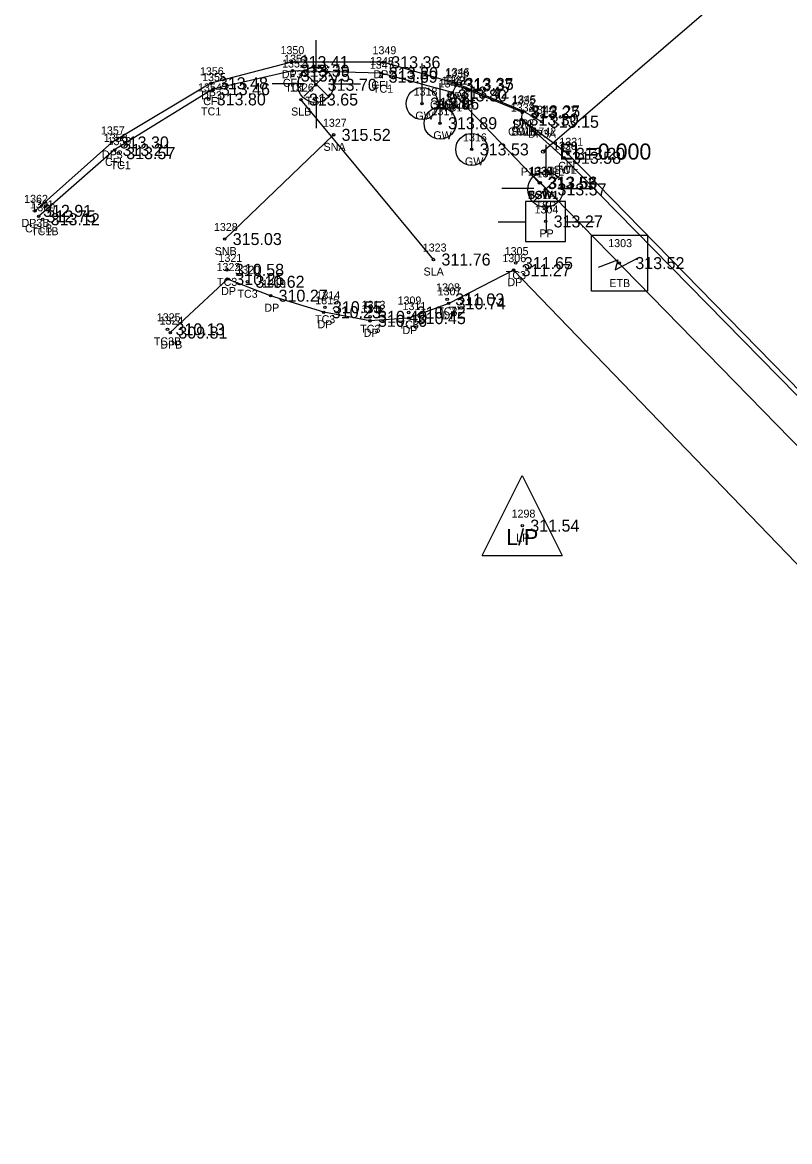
# Model space of a CAD drawing. Extents: x 1970076 to 1971136, y 803126 to 804215.
# Drawn here: x 1970552 to 1970647.9, y 803383.6 to 803523.4 of the extents above; entities that cross this region are included whole.
import ezdxf

# ---------------------------------------------------------------- set-up
doc = ezdxf.new("R2010")
doc.units = 0
for name, color, linetype in [('RD_EX_BldgApp', 7, 'Continuous'), ('RD_EX_BldgApp_txCode', 7, 'Continuous'), ('RD_EX_Conc', 7, 'Continuous'), ('RD_EX_Conc_txCode', 7, 'Continuous'), ('RD_EX_DR_Pipe', 7, 'Continuous'), ('RD_EX_DR_Pipe_txCode', 7, 'Continuous'), ('RD_EX_Driveway', 7, 'Continuous'), ('RD_EX_Driveway_txCode', 7, 'Continuous'), ('RD_EX_SU_Pole', 7, 'Continuous'), ('RD_EX_TX_BldgApp_ELEV', 7, 'Continuous'), ('RD_EX_TX_Conc_ELEV', 7, 'Continuous'), ('RD_EX_TX_Driveway_ELEV', 7, 'Continuous'), ('RD_EX_TX_UT_ELEV', 7, 'Continuous'), ('RD_EX_TX_VEG_ELEV', 7, 'Continuous'), ('RD_EX_UT', 7, 'Continuous'), ('RD_EX_UT_txCode', 7, 'Continuous'), ('RD_EX_VEG', 7, 'Continuous'), ('RD_EX_VEG_txCode', 7, 'Continuous'), ('RD_HC_Survey_ELEV', 7, 'Continuous'), ('RD_SMD_Locator', 7, 'Continuous'), ('RD_TX_Pipe_ElevEX', 7, 'Continuous')]:
    doc.layers.add(name, color=color, linetype=linetype)

msp = doc.modelspace()

# ---------------------------------------------------------------- linework, layer by layer
at = {"layer": 'RD_EX_BldgApp'}
msp.add_line((1970590.93, 803509.37), (1970577.32, 803496.35), dxfattribs=at)
at = {"layer": 'RD_EX_Conc'}
for points in [[(1970605.78, 803514.65), (1970596.84, 803517.08), (1970585.8, 803517.37), (1970575.84, 803515.08), (1970563.55, 803507.49), (1970554.05, 803499.18)], [(1970741.86, 803386.33), (1970712.13, 803414.37), (1970659.98, 803465.47), (1970619.72, 803506.5), (1970614.41, 803511.28), (1970614.52, 803512.19), (1970606.23, 803515.56), (1970605.78, 803514.65)], [(1970738.49, 803383.57), (1970738.35, 803383.61), (1970709.03, 803411.19), (1970656.75, 803462.47), (1970616.75, 803503.4), (1970616.66, 803503.34), (1970605.78, 803514.65)], [(1970742.28, 803386.82), (1970712.72, 803414.79), (1970660.39, 803465.9), (1970620.21, 803507), (1970614.41, 803511.28)]]:
    msp.add_lwpolyline(points, dxfattribs=at)
at = {"layer": 'RD_EX_DR_Pipe'}
msp.add_line((1970664.76, 803548.24), (1970617.11, 803507.28), dxfattribs=at)
at = {"layer": 'RD_EX_Driveway'}
for points in [[(1970616.95, 803511), (1970614.61, 803512.31), (1970606.31, 803515.73), (1970597.14, 803518.44), (1970585.68, 803518.45), (1970575.59, 803515.81), (1970563.2, 803508.42), (1970553.62, 803499.87)], [(1970649.82, 803454.73), (1970613.43, 803492.46), (1970605.31, 803488.31), (1970600.32, 803486.47), (1970595.47, 803486.13), (1970589.7, 803487.2), (1970583.05, 803489.27), (1970577.65, 803491.35), (1970570.52, 803484.66)]]:
    msp.add_lwpolyline(points, dxfattribs=at)
at = {"layer": 'RD_EX_SU_Pole'}
for p, q in [((1970588.76, 803517.19), (1970588.76, 803521.19)), ((1970590.26, 803517.19), (1970587.26, 803514.19)), ((1970587.26, 803517.19), (1970590.26, 803514.19)), ((1970587.23, 803515.74), (1970583.23, 803515.74)), ((1970590.27, 803515.75), (1970594.29, 803515.75)), ((1970588.76, 803514.19), (1970588.76, 803510.19)), ((1970617.48, 803504.12), (1970617.48, 803508.12)), ((1970618.98, 803504.12), (1970615.98, 803501.12)), ((1970615.98, 803504.12), (1970618.98, 803501.12)), ((1970615.96, 803502.67), (1970611.96, 803502.67)), ((1970619, 803502.68), (1970623.01, 803502.68)), ((1970617.48, 803501.12), (1970617.48, 803497.12))]:
    msp.add_line(p, q, dxfattribs=at)
for centre in [(1970588.69, 803515.62), (1970617.41, 803502.55)]:
    msp.add_circle(centre, 2.22, dxfattribs=at)
at = {"layer": 'RD_EX_UT'}
for p, q in [((1970601.99, 803513.27), (1970601.99, 803518.27)), ((1970604.23, 803510.82), (1970604.23, 803515.82)), ((1970608.19, 803507.55), (1970608.19, 803512.55)), ((1970619.92, 803501.06), (1970614.92, 803501.06)), ((1970614.92, 803501.06), (1970614.92, 803496.06)), ((1970619.92, 803496.06), (1970619.92, 803501.06)), ((1970611.49, 803498.5), (1970614.96, 803498.5)), ((1970619.85, 803498.5), (1970623.49, 803498.5)), ((1970614.92, 803496.06), (1970619.92, 803496.06)), ((1970609.51, 803456.81), (1970614.51, 803466.81)), ((1970614.51, 803466.81), (1970619.51, 803456.81)), ((1970609.51, 803456.81), (1970619.51, 803456.81))]:
    msp.add_line(p, q, dxfattribs=at)
msp.add_lwpolyline([(1970623.14, 803489.84), (1970623.14, 803496.84), (1970630.14, 803496.84), (1970630.14, 803489.84)], close=True, dxfattribs=at)
msp.add_lwpolyline([(1970624.04, 803492.84), (1970626.46, 803493.74), (1970626.11, 803492.49), (1970629.16, 803494.09)], dxfattribs=at)
for centre in [(1970601.99, 803513.27), (1970604.23, 803510.82), (1970608.19, 803507.55)]:
    msp.add_circle(centre, 2, dxfattribs=at)
at = {"layer": 'RD_EX_VEG'}
msp.add_line((1970603.41, 803493.79), (1970586.85, 803513.78), dxfattribs=at)
at = {"layer": 'RD_SMD_Locator'}
for centre, radius in [((1970585.68, 803518.45), 0.15), ((1970585.8, 803517.37), 0.15), ((1970596.84, 803517.08), 0.15), ((1970597.14, 803518.44), 0.15), ((1970575.59, 803515.81), 0.15), ((1970585.83, 803516.78), 0.15), ((1970596.8, 803516.63), 0.15), ((1970606.31, 803515.73), 0.15), ((1970575.84, 803515.08), 0.15), ((1970588.69, 803515.62), 0.15), ((1970605.45, 803514.29), 0.15), ((1970605.78, 803514.65), 0.15), ((1970605.78, 803514.65), 0.15), ((1970605.78, 803514.65), 0.15), ((1970606.23, 803515.56), 0.15), ((1970575.32, 803513.8), 0.15), ((1970586.85, 803513.78), 0.15), ((1970601.99, 803513.27), 0.15), ((1970614.52, 803512.19), 0.15), ((1970614.61, 803512.31), 0.15), ((1970604.23, 803510.82), 0.15), ((1970614.41, 803511.28), 0.15), ((1970614.41, 803511.28), 0.15), ((1970614.41, 803511.28), 0.15), ((1970616.95, 803511), 0.15), ((1970590.93, 803509.37), 0.15), ((1970563.2, 803508.42), 0.15), ((1970563.55, 803507.49), 0.15), ((1970608.19, 803507.55), 0.15), ((1970617.11, 803507.28), 0.2), ((1970564.01, 803507.08), 0.15), ((1970619.72, 803506.5), 0.15), ((1970619.72, 803506.5), 0.15), ((1970620.21, 803507), 0.15), ((1970616.66, 803503.34), 0.15), ((1970616.66, 803503.34), 0.15), ((1970616.75, 803503.4), 0.15), ((1970617.41, 803502.55), 0.15), ((1970553.62, 803499.87), 0.15), ((1970554.05, 803499.18), 0.15), ((1970554.57, 803498.82), 0.15), ((1970617.43, 803498.55), 0.15), ((1970577.32, 803496.35), 0.15), ((1970603.41, 803493.79), 0.15), ((1970613.7, 803493.34), 0.15), ((1970626.64, 803493.34), 0.15), ((1970577.6, 803492.5), 0.15), ((1970613.43, 803492.46), 0.15), ((1970577.65, 803491.35), 0.15), ((1970580.16, 803491.01), 0.15), ((1970583.05, 803489.27), 0.15), ((1970589.85, 803487.83), 0.15), ((1970605.12, 803488.81), 0.15), ((1970605.31, 803488.31), 0.15), ((1970589.7, 803487.2), 0.15), ((1970595.49, 803486.63), 0.15), ((1970600.31, 803487.17), 0.15), ((1970600.32, 803486.47), 0.15), ((1970570.17, 803485.07), 0.15), ((1970595.47, 803486.13), 0.15), ((1970570.52, 803484.66), 0.15), ((1970614.51, 803460.54), 0.15)]:
    msp.add_circle(centre, radius, dxfattribs=at)

# ---------------------------------------------------------------- texts
at = {"layer": 'RD_EX_BldgApp_txCode'}
for s, p in [('1327', (1970589.59, 803510.37)), ('SNA', (1970589.67, 803507.37)), ('1328', (1970575.97, 803497.35)), ('SNB', (1970576.07, 803494.35))]:
    msp.add_text(s, height=1, dxfattribs=at).set_placement(p)
at = {"layer": 'RD_EX_Conc_txCode'}
for s, p in [('1352', (1970584.49, 803517.78)), ('1351', (1970584.74, 803518.37)), ('1347', (1970595.45, 803517.63)), ('1348', (1970595.49, 803518.08)), ('1336', (1970604.86, 803516.56)), ('1354', (1970573.98, 803514.8)), ('1355', (1970574.49, 803516.08)), ('CFL', (1970584.59, 803515.37)), ('CFL', (1970595.64, 803515.08)), ('1340', (1970604.06, 803515.29)), ('1342', (1970604.43, 803515.65)), ('1343', (1970604.43, 803515.65)), ('1341', (1970604.72, 803515.65)), ('TC1', (1970584.87, 803514.78)), ('TC1', (1970595.84, 803514.63)), ('SWL', (1970604.94, 803513.56)), ('CFL', (1970574.63, 803513.08)), ('CFLA 12', (1970602.98, 803512.65)), ('BSW1B', (1970603.83, 803512.65)), ('SWLB', (1970604.02, 803512.65)), ('TC1', (1970604.49, 803512.29)), ('1332', (1970613.07, 803512.28)), ('1333', (1970613.07, 803512.28)), ('1334', (1970613.07, 803512.28)), ('1335', (1970613.17, 803513.19)), ('TC1', (1970574.36, 803511.8)), ('CFLB', (1970612.73, 803509.28)), ('TC1B', (1970612.98, 803509.28)), ('SWL', (1970613.12, 803509.28)), ('SWL', (1970613.23, 803510.19)), ('1358', (1970562.2, 803508.49)), ('1359', (1970562.67, 803508.08)), ('1331', (1970619.14, 803508)), ('1330', (1970618.34, 803507.5)), ('1329', (1970618.38, 803507.5)), ('CFL', (1970562.35, 803505.49)), ('TC1', (1970563.05, 803505.08)), ('1338', (1970615.32, 803504.34)), ('1339', (1970615.32, 803504.34)), ('1337', (1970615.4, 803504.4)), ('SWL', (1970618.43, 803504.5)), ('TC1', (1970618.76, 803504.5)), ('CFL', (1970619, 803505)), ('TC1A', (1970615.22, 803501.34)), ('BSW1', (1970615.18, 803501.34)), ('BSW1', (1970615.27, 803501.4)), ('1361', (1970552.96, 803500.18)), ('1360', (1970553.16, 803499.82)), ('CFLB', (1970552.37, 803497.18)), ('TC1B', (1970553.13, 803496.82)), ('1305', (1970612.31, 803494.34)), ('1321', (1970576.54, 803493.5)), ('1320', (1970578.77, 803492.01)), ('TC3', (1970612.45, 803491.34)), ('TC3', (1970576.36, 803490.5)), ('1308', (1970603.74, 803489.81)), ('TC3', (1970578.91, 803489.01)), ('1314', (1970588.79, 803488.83)), ('1313', (1970594.43, 803487.63)), ('1309', (1970598.92, 803488.17)), ('1325', (1970568.82, 803486.07)), ('TC3', (1970588.61, 803485.83)), ('TC3', (1970603.88, 803486.81)), ('TC3', (1970594.25, 803484.63)), ('TC3', (1970599.06, 803485.17)), ('TC3B', (1970568.45, 803483.07))]:
    msp.add_text(s, height=1, dxfattribs=at).set_placement(p)
at = {"layer": 'RD_EX_DR_Pipe_txCode'}
for s, p in [('1742', (1970615.77, 803509.28)), ('P1B NFL', (1970614.32, 803504.28))]:
    msp.add_text(s, height=1, dxfattribs=at).set_placement(p)
at = {"layer": 'RD_EX_Driveway_txCode'}
for s, p in [('1350', (1970584.29, 803519.45)), ('1349', (1970595.79, 803519.44)), ('1356', (1970574.22, 803516.81)), ('DP3', (1970584.45, 803516.45)), ('DP3', (1970595.91, 803516.44)), ('1346', (1970604.94, 803516.73)), ('DP3', (1970574.36, 803513.81)), ('DP3', (1970605.08, 803513.73)), ('1345', (1970613.26, 803513.31)), ('1344', (1970615.6, 803512)), ('1357', (1970561.85, 803509.42)), ('DP3', (1970613.38, 803510.31)), ('DP3A', (1970615.23, 803509)), ('DP3', (1970561.97, 803506.42)), ('1362', (1970552.25, 803500.87)), ('DP3B', (1970551.92, 803497.87)), ('1306', (1970612.02, 803493.46)), ('1322', (1970576.3, 803492.35)), ('1319', (1970581.99, 803490.27)), ('DP', (1970612.65, 803490.46)), ('DP', (1970576.87, 803489.35)), ('1307', (1970603.93, 803489.31)), ('DP', (1970582.27, 803487.27)), ('1315', (1970588.64, 803488.2)), ('1312', (1970594.41, 803487.13)), ('1311', (1970599.54, 803487.47)), ('1324', (1970569.18, 803485.66)), ('DP', (1970604.53, 803486.31)), ('DP', (1970588.92, 803485.2)), ('DP', (1970594.69, 803484.13)), ('DP', (1970599.54, 803484.47)), ('DPB', (1970569.27, 803482.66))]:
    msp.add_text(s, height=1, dxfattribs=at).set_placement(p)
at = {"layer": 'RD_EX_TX_BldgApp_ELEV'}
for s, p in [('315.52', (1970591.93, 803508.62)), ('315.03', (1970578.32, 803495.6))]:
    msp.add_text(s, height=1.5, dxfattribs=at).set_placement(p)
at = {"layer": 'RD_EX_TX_Conc_ELEV'}
for s, p in [('313.39', (1970586.8, 803516.62)), ('313.75', (1970586.83, 803516.03)), ('313.69', (1970597.8, 803515.88)), ('313.30', (1970597.84, 803516.33)), ('313.46', (1970576.84, 803514.33)), ('313.37', (1970607.23, 803514.81)), ('313.80', (1970576.32, 803513.05)), ('313.80', (1970606.45, 803513.54)), ('313.42', (1970606.78, 803513.9)), ('313.42', (1970606.78, 803513.9)), ('313.42', (1970606.78, 803513.9)), ('313.30', (1970615.41, 803510.53)), ('313.30', (1970615.41, 803510.53)), ('313.30', (1970615.41, 803510.53)), ('313.27', (1970615.52, 803511.44)), ('313.21', (1970564.55, 803506.74)), ('313.57', (1970565.01, 803506.33)), ('313.20', (1970621.21, 803506.25)), ('313.58', (1970620.72, 803505.75)), ('313.58', (1970620.72, 803505.75)), ('313.53', (1970617.66, 803502.59)), ('313.53', (1970617.66, 803502.59)), ('313.56', (1970617.75, 803502.65)), ('312.75', (1970555.05, 803498.43)), ('313.12', (1970555.57, 803498.07)), ('311.65', (1970614.7, 803492.59)), ('310.58', (1970578.6, 803491.75)), ('310.62', (1970581.16, 803490.26)), ('311.03', (1970606.12, 803488.06)), ('310.55', (1970590.85, 803487.08)), ('310.72', (1970601.31, 803486.42)), ('310.40', (1970596.49, 803485.88)), ('310.13', (1970571.17, 803484.32))]:
    msp.add_text(s, height=1.5, dxfattribs=at).set_placement(p)
at = {"layer": 'RD_EX_TX_Driveway_ELEV'}
for s, p in [('313.41', (1970586.68, 803517.7)), ('313.36', (1970598.14, 803517.69)), ('313.48', (1970576.59, 803515.06)), ('313.35', (1970607.31, 803514.98)), ('313.25', (1970615.61, 803511.56)), ('313.15', (1970617.95, 803510.25)), ('313.30', (1970564.2, 803507.67)), ('312.91', (1970554.62, 803499.12)), ('310.25', (1970578.65, 803490.6)), ('311.27', (1970614.43, 803491.71)), ('310.27', (1970584.05, 803488.52)), ('310.23', (1970590.7, 803486.45)), ('310.74', (1970606.31, 803487.56)), ('310.16', (1970596.47, 803485.38)), ('310.45', (1970601.32, 803485.72)), ('309.81', (1970571.52, 803483.91))]:
    msp.add_text(s, height=1.5, dxfattribs=at).set_placement(p)
at = {"layer": 'RD_EX_TX_UT_ELEV'}
for s, p in [('313.70', (1970590.19, 803514.87)), ('313.86', (1970602.99, 803512.52)), ('313.89', (1970605.23, 803510.07)), ('313.53', (1970609.19, 803506.8)), ('313.57', (1970618.91, 803501.8)), ('313.52', (1970628.64, 803492.59)), ('311.54', (1970615.51, 803459.79))]:
    msp.add_text(s, height=1.5, dxfattribs=at).set_placement(p)
at = {"layer": 'RD_EX_TX_VEG_ELEV'}
for s, p in [('313.65', (1970587.85, 803513.03)), ('311.76', (1970604.41, 803493.04))]:
    msp.add_text(s, height=1.5, dxfattribs=at).set_placement(p)
at = {"layer": 'RD_EX_UT'}
msp.add_text('L/P', height=2, dxfattribs=at).set_placement((1970612.5, 803458.1))
at = {"layer": 'RD_EX_UT_txCode'}
for s, p in [('1353', (1970587.34, 803517.12)), ('1318', (1970600.93, 803514.27)), ('TSP', (1970587.42, 803513.12)), ('GW', (1970601.15, 803511.27)), ('1317', (1970603.17, 803511.82)), ('GW', (1970603.39, 803508.82)), ('1316', (1970607.1, 803508.55)), ('GW', (1970607.34, 803505.55)), ('1310', (1970616.31, 803504.05)), ('1304', (1970616.04, 803499.55)), ('TSP', (1970616.15, 803500.05)), ('PP', (1970616.65, 803496.55)), ('1303', (1970625.25, 803495.34)), ('ETB', (1970625.39, 803490.34)), ('1298', (1970613.17, 803461.54)), ('LP', (1970613.76, 803458.54))]:
    msp.add_text(s, height=1, dxfattribs=at).set_placement(p)
at = {"layer": 'RD_EX_VEG_txCode'}
for s, p in [('1326', (1970585.48, 803514.78)), ('SLB', (1970585.62, 803511.78)), ('1323', (1970602.07, 803494.79)), ('SLA', (1970602.17, 803491.79))]:
    msp.add_text(s, height=1, dxfattribs=at).set_placement(p)
at = {"layer": 'RD_HC_Survey_ELEV'}
msp.add_text('313.27', height=1.5, dxfattribs=at).set_placement((1970618.43, 803497.8))
at = {"layer": 'RD_TX_Pipe_ElevEX'}
msp.add_text('EL=0.000', height=2, dxfattribs=at).set_placement((1970619.11, 803506.28))

doc.saveas('drawing.dxf')
